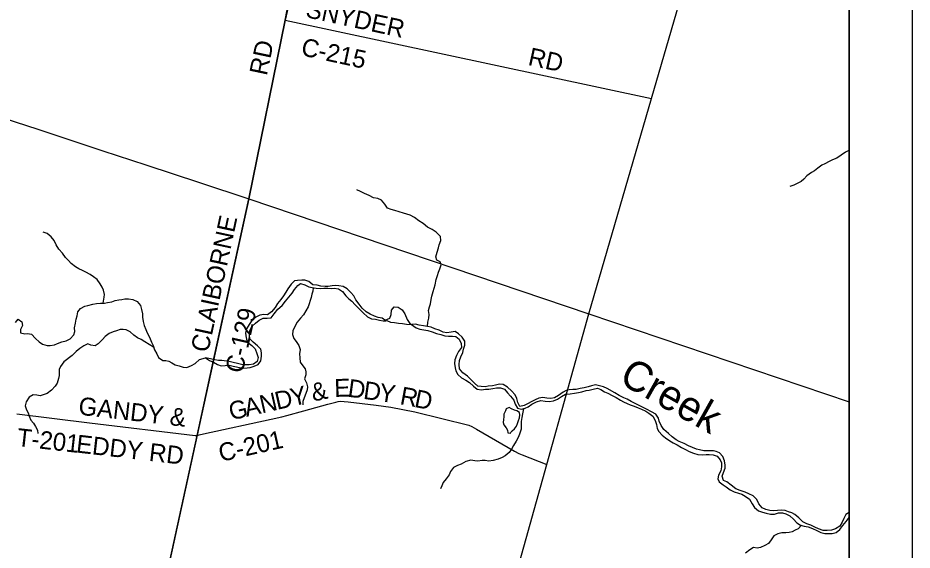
# Model space of a CAD drawing. Extents: x 0 to 34, y 0 to 22.
# Drawn here: x 7.582 to 9, y 16.562 to 17.405 of the extents above; entities that cross this region are included whole.
import ezdxf

# ---------------------------------------------------------------- set-up
doc = ezdxf.new("R2010")
doc.units = 0
for name, color, linetype in [('GM_X_Corporation', 7, 'Continuous'), ('GM_X_County_Road', 7, 'Continuous'), ('GM_X_County_Road_Text', 7, 'Continuous'), ('GM_X_Minor_Lake', 7, 'Continuous'), ('GM_X_Minor_River', 7, 'Continuous'), ('GM_X_Minor_River_Text', 7, 'Continuous'), ('GM_X_Township_Road', 7, 'Continuous'), ('GM_X_Township_Road_Text', 7, 'Continuous'), ('SH_Data', 7, 'Continuous')]:
    doc.layers.add(name, color=color, linetype=linetype)

msp = doc.modelspace()

# ---------------------------------------------------------------- linework, layer by layer
at = {"layer": 'GM_X_Corporation'}
for points in [[(2.7052, 14.1), (8.9, 14.1), (8.9, 20.9), (3.3687, 20.9)], [(8.0146, 17.4385), (8.0061, 17.4015), (7.9483, 17.1186), (7.8667, 16.7439), (7.8171, 16.5163), (7.6624, 15.7725), (7.761, 15.7513), (7.7853, 15.4515), (7.8145, 15.0705), (8.0549, 15.0964), (8.0668, 14.9397), (8.0887, 14.5411), (8.0986, 14.3711), (8.2117, 14.3797), (8.4217, 14.3956), (8.5553, 14.4065), (8.6255, 14.4123), (8.6725, 14.4163), (8.8777, 14.4334), (8.8814, 14.4337), (8.9, 14.4352), (8.9, 17.4353)]]:
    msp.add_lwpolyline(points, dxfattribs=at)
at = {"layer": 'GM_X_County_Road'}
for p, q in [((7.9484, 17.1184), (8.0062, 17.4013)), ((8.0062, 17.4013), (8.5866, 17.2775)), ((7.8943, 16.8702), (7.9484, 17.1184)), ((7.8901, 16.8507), (7.8943, 16.8702))]:
    msp.add_line(p, q, dxfattribs=at)
for points in [[(8.3418, 16.4142), (8.4211, 16.6978), (8.4874, 16.9362), (8.5866, 17.2775), (8.6502, 17.4955), (8.6767, 17.5875), (8.6775, 17.5904)], [(8.0062, 17.4013), (8.0122, 17.4314), (8.0127, 17.4363), (8.0124, 17.4394)], [(7.1249, 17.408), (7.1305, 17.405), (7.1344, 17.4026), (7.1425, 17.3964), (7.1511, 17.391), (7.1923, 17.3668), (7.2004, 17.3628), (7.21, 17.3587), (7.3163, 17.3189), (7.3259, 17.3164), (7.348, 17.3113), (7.3805, 17.3035), (7.3867, 17.3018), (7.3932, 17.2999), (7.6139, 17.2289), (7.6678, 17.2109), (7.717, 17.1947), (7.785, 17.1725), (7.8702, 17.1443), (7.9484, 17.1184)], [(7.9484, 17.1184), (8.4874, 16.9362), (8.9, 16.7968)], [(7.6636, 15.7772), (7.8172, 16.516), (7.8668, 16.7436), (7.8901, 16.8507)], [(7.8668, 16.7436), (7.8699, 16.7446), (7.8766, 16.7459), (7.984, 16.7692), (8.001, 16.7731), (8.009, 16.775), (8.0359, 16.7825), (8.0549, 16.7877), (8.0737, 16.793), (8.0862, 16.7963), (8.0899, 16.7971), (8.0946, 16.7977), (8.0994, 16.7976), (8.1058, 16.7969), (8.1503, 16.7916), (8.1739, 16.7886), (8.2115, 16.781), (8.2971, 16.7596), (8.3021, 16.7576), (8.3096, 16.7535), (8.3698, 16.7186), (8.3768, 16.7149), (8.382, 16.7129), (8.4211, 16.6978)]]:
    msp.add_lwpolyline(points, dxfattribs=at)
at = {"layer": 'GM_X_Minor_Lake'}
for points in [[(8.3564, 16.7858), (8.3553, 16.7824), (8.353, 16.7773), (8.3528, 16.7729), (8.3522, 16.7686), (8.3518, 16.764), (8.3529, 16.7602), (8.3567, 16.7557), (8.3584, 16.7519), (8.3589, 16.7475), (8.3631, 16.7473), (8.3645, 16.7493)], [(8.3645, 16.7493), (8.3658, 16.7511), (8.3696, 16.7541), (8.3726, 16.7581), (8.3745, 16.7624), (8.3762, 16.767), (8.3778, 16.7717), (8.3782, 16.7763), (8.3774, 16.7801), (8.3735, 16.7824), (8.3695, 16.7837), (8.3651, 16.7858), (8.361, 16.7879), (8.3564, 16.7858)]]:
    msp.add_lwpolyline(points, dxfattribs=at)
at = {"layer": 'GM_X_Minor_River'}
for points in [[(8.9, 17.1952), (8.8999, 17.1951), (8.8942, 17.1921), (8.8875, 17.1877), (8.8809, 17.183), (8.874, 17.1802), (8.8685, 17.1774), (8.8619, 17.1738), (8.8571, 17.1715), (8.8507, 17.167), (8.8453, 17.1628), (8.8404, 17.16), (8.8332, 17.1549), (8.8286, 17.1498), (8.8239, 17.146), (8.8187, 17.1434), (8.8125, 17.1402), (8.806, 17.1381)], [(8.2316, 16.9164), (8.2324, 16.9229), (8.2341, 16.9295), (8.2342, 16.9352), (8.2336, 16.9417), (8.235, 16.9474), (8.2363, 16.9521), (8.2377, 16.9587), (8.2388, 16.964), (8.2409, 16.9714), (8.2423, 16.9769), (8.244, 16.9824), (8.2457, 16.9906), (8.2477, 16.9972), (8.2494, 17.0025), (8.2513, 17.0073), (8.2534, 17.0137), (8.2521, 17.0188), (8.2463, 17.0213), (8.2448, 17.0266), (8.2472, 17.034), (8.249, 17.0407), (8.2505, 17.0456), (8.253, 17.0522), (8.2525, 17.0585), (8.2457, 17.0657), (8.2394, 17.0697), (8.2319, 17.0737), (8.2249, 17.0793), (8.2182, 17.0835), (8.2113, 17.0886), (8.2041, 17.0926), (8.199, 17.0942), (8.1935, 17.0955), (8.187, 17.0976), (8.1798, 17.0997), (8.1743, 17.1016), (8.1681, 17.1038), (8.1639, 17.1102), (8.1588, 17.1163), (8.1532, 17.119), (8.1462, 17.1202), (8.1392, 17.1238), (8.132, 17.127), (8.1257, 17.1299), (8.1197, 17.1328)], [(7.7175, 16.9533), (7.7193, 16.9624), (7.7195, 16.9671), (7.7184, 16.9737), (7.7162, 16.9785), (7.7131, 16.984), (7.7079, 16.9905), (7.7024, 16.9949), (7.6969, 16.9987), (7.6903, 17.0023), (7.6846, 17.005), (7.6793, 17.0077), (7.6736, 17.0109), (7.6668, 17.0159), (7.6625, 17.0208), (7.658, 17.0256), (7.6529, 17.0322), (7.6476, 17.0389), (7.6432, 17.0457), (7.64, 17.0526), (7.6351, 17.0581), (7.6287, 17.0634), (7.6223, 17.0657)], [(8.1655, 16.9254), (8.1598, 16.9294), (8.1537, 16.9304), (8.1475, 16.9325), (8.1409, 16.9358), (8.1346, 16.9394), (8.1284, 16.9453), (8.1233, 16.9514), (8.1184, 16.9582), (8.1152, 16.9649), (8.1101, 16.9702), (8.1043, 16.9757), (8.098, 16.9794), (8.0914, 16.9807), (8.0866, 16.9809), (8.0806, 16.9804), (8.0745, 16.9796), (8.0694, 16.9795), (8.0629, 16.9799), (8.0569, 16.9816), (8.0502, 16.9824), (8.0434, 16.9873), (8.0372, 16.9898), (8.0323, 16.9897), (8.0258, 16.9891), (8.0211, 16.9886), (8.0159, 16.9833), (8.0106, 16.9759), (8.007, 16.9704), (8.0035, 16.9647), (7.999, 16.9589), (7.994, 16.9528), (7.9902, 16.9462), (7.9843, 16.9394), (7.9782, 16.9346), (7.9721, 16.9352), (7.9659, 16.9339), (7.9594, 16.9311), (7.9533, 16.9258), (7.9489, 16.9196), (7.9449, 16.9126), (7.9434, 16.9059), (7.9439, 16.9012), (7.9447, 16.8963), (7.9467, 16.8906), (7.9532, 16.886), (7.9586, 16.8806), (7.9613, 16.8732), (7.9631, 16.8668), (7.9618, 16.8605), (7.9557, 16.8564), (7.9489, 16.8553), (7.9419, 16.8557), (7.9371, 16.8562), (7.9305, 16.8574), (7.9237, 16.8593), (7.9174, 16.8607), (7.9055, 16.8621), (7.9006, 16.8625), (7.8947, 16.8634), (7.888, 16.8652), (7.8801, 16.8663)], [(7.8801, 16.8663), (7.886, 16.8621), (7.8924, 16.8596), (7.8986, 16.8562), (7.9047, 16.8541), (7.9108, 16.8543), (7.9172, 16.8548), (7.9238, 16.8535), (7.9288, 16.8523), (7.9356, 16.8506), (7.9403, 16.85), (7.946, 16.8505), (7.9509, 16.8511), (7.9572, 16.8531), (7.9633, 16.856), (7.9675, 16.8618), (7.9688, 16.869), (7.9685, 16.8742), (7.9674, 16.8804), (7.9621, 16.8854), (7.9555, 16.8913), (7.9494, 16.897), (7.9496, 16.9029), (7.9502, 16.9091), (7.9531, 16.916), (7.959, 16.9216), (7.9651, 16.926), (7.9715, 16.9295), (7.9778, 16.9295), (7.9841, 16.9299), (7.9888, 16.9363), (7.9947, 16.9437), (8.0012, 16.9497), (8.0069, 16.9562), (8.0119, 16.9626), (8.0172, 16.9688), (8.021, 16.9747), (8.026, 16.9811), (8.0307, 16.9845), (8.0373, 16.9824), (8.0436, 16.9792), (8.0487, 16.978), (8.0555, 16.9767), (8.0616, 16.9763), (8.0675, 16.9768), (8.0737, 16.9768), (8.0788, 16.9766), (8.0838, 16.9768), (8.0908, 16.976), (8.0972, 16.9716), (8.1021, 16.9649), (8.107, 16.96), (8.1119, 16.9564), (8.1172, 16.9503), (8.1297, 16.9377), (8.1365, 16.9314), (8.1431, 16.9285), (8.1494, 16.9276), (8.1556, 16.926), (8.1615, 16.9251), (8.1655, 16.9254)], [(8.0506, 16.9776), (8.0498, 16.9723), (8.0483, 16.9676), (8.0471, 16.9621), (8.046, 16.9574), (8.0444, 16.9522), (8.0427, 16.9473), (8.0391, 16.9409), (8.0351, 16.9346), (8.0307, 16.9295), (8.0254, 16.9229), (8.0215, 16.9161), (8.0183, 16.9095), (8.0175, 16.9036), (8.0198, 16.8971), (8.0235, 16.8922), (8.0277, 16.8863), (8.0299, 16.8796), (8.029, 16.873), (8.0295, 16.8665), (8.0298, 16.8599), (8.0342, 16.8536), (8.0378, 16.8489), (8.0389, 16.8441), (8.0387, 16.8394), (8.0369, 16.8331), (8.0398, 16.827), (8.0414, 16.8208), (8.041, 16.816), (8.0389, 16.81), (8.0363, 16.8031), (8.0343, 16.7971), (8.0341, 16.7921)], [(7.6737, 16.9214), (7.6746, 16.928), (7.6764, 16.9329), (7.6777, 16.9394), (7.6817, 16.9447), (7.6884, 16.9482), (7.6933, 16.9497), (7.7011, 16.9514), (7.707, 16.9524), (7.7134, 16.9531), (7.7195, 16.9534), (7.7244, 16.954), (7.7314, 16.9555), (7.7366, 16.9572), (7.7422, 16.9583), (7.7474, 16.9592), (7.7521, 16.9598), (7.758, 16.9599), (7.7648, 16.9592), (7.7716, 16.9557), (7.7767, 16.9496), (7.7784, 16.9432), (7.7799, 16.936), (7.7802, 16.9308), (7.7812, 16.9242), (7.7827, 16.9177), (7.7853, 16.9113), (7.7872, 16.9063), (7.7898, 16.9016), (7.792, 16.8966), (7.7945, 16.8913), (7.7967, 16.886), (7.799, 16.8792), (7.8026, 16.8729), (7.8054, 16.867), (7.812, 16.8624), (7.8169, 16.8622), (7.8217, 16.8612), (7.8266, 16.8587), (7.8317, 16.8553), (7.838, 16.8536), (7.8446, 16.8515), (7.8503, 16.8514), (7.8575, 16.8543), (7.8636, 16.8577), (7.8702, 16.8637), (7.8801, 16.8663)], [(8.1647, 16.926), (8.1719, 16.9294), (8.1744, 16.9354), (8.1748, 16.9419), (8.179, 16.9472), (8.1853, 16.9466), (8.1915, 16.9426), (8.1957, 16.9363), (8.1993, 16.9274), (8.2046, 16.9196)], [(7.5787, 16.9227), (7.5829, 16.9276), (7.5889, 16.9238), (7.5895, 16.9175), (7.5868, 16.9112), (7.5866, 16.9063), (7.5932, 16.9044), (7.5979, 16.9051), (7.6038, 16.9038), (7.6106, 16.8973), (7.6159, 16.8918), (7.6214, 16.8882), (7.6288, 16.886), (7.6337, 16.886), (7.6403, 16.8873), (7.6451, 16.8894), (7.6519, 16.892), (7.6589, 16.8935), (7.6652, 16.8965), (7.6711, 16.9028), (7.6727, 16.9083), (7.6723, 16.9143), (7.6737, 16.9214)], [(8.1655, 16.9254), (8.1672, 16.9256), (8.1731, 16.9233), (8.1795, 16.9225), (8.1859, 16.9215), (8.1922, 16.9208), (8.1983, 16.9198), (8.2062, 16.9196)], [(8.7065, 16.6702), (8.7012, 16.6723), (8.6991, 16.6791), (8.7011, 16.685), (8.7034, 16.6916), (8.7038, 16.6966), (8.7025, 16.7032), (8.6998, 16.7104), (8.6947, 16.7161), (8.6896, 16.7184), (8.6849, 16.719), (8.6796, 16.7194), (8.6747, 16.7191), (8.6699, 16.7191), (8.6631, 16.7206), (8.6582, 16.722), (8.6519, 16.7243), (8.6455, 16.7273), (8.6385, 16.7308), (8.6309, 16.7342), (8.626, 16.7367), (8.6194, 16.7414), (8.6137, 16.7466), (8.6063, 16.7531), (8.602, 16.7593), (8.5992, 16.7662), (8.5981, 16.7709), (8.5936, 16.7772), (8.5871, 16.7808), (8.5788, 16.7852), (8.5727, 16.7885), (8.5674, 16.7911), (8.5612, 16.7942), (8.5546, 16.7975), (8.5481, 16.8009), (8.5432, 16.8034), (8.5357, 16.8068), (8.5288, 16.811), (8.5167, 16.8179), (8.5107, 16.8204), (8.5042, 16.8223), (8.4982, 16.8236), (8.4915, 16.8223), (8.4864, 16.8208), (8.4802, 16.819), (8.4737, 16.8182), (8.4673, 16.8165), (8.4619, 16.8166), (8.4566, 16.8158), (8.4517, 16.8149), (8.4466, 16.8123), (8.4395, 16.8066), (8.4331, 16.8034), (8.4272, 16.8023), (8.4209, 16.8029), (8.4145, 16.8036), (8.4082, 16.8029), (8.4022, 16.8001), (8.3959, 16.7967), (8.3911, 16.7942), (8.3849, 16.7909), (8.3784, 16.7895), (8.3748, 16.7958), (8.3732, 16.8019), (8.3705, 16.8078), (8.3651, 16.8143), (8.3588, 16.8202), (8.3518, 16.8244), (8.3458, 16.8248), (8.3397, 16.8231), (8.3349, 16.8223), (8.3281, 16.8216), (8.3232, 16.8207), (8.3167, 16.8209), (8.3118, 16.8219), (8.3061, 16.8264), (8.3009, 16.8319), (8.295, 16.8375), (8.2876, 16.843), (8.2823, 16.8491), (8.2822, 16.8559), (8.2824, 16.8622), (8.2845, 16.8679), (8.2876, 16.8749), (8.2889, 16.88), (8.2908, 16.8868), (8.2907, 16.8931), (8.2865, 16.8992), (8.281, 16.9047), (8.2754, 16.9083), (8.2691, 16.9072), (8.2625, 16.9059), (8.2568, 16.9072), (8.25, 16.9101), (8.2435, 16.9126), (8.2375, 16.9151), (8.2316, 16.9164), (8.2254, 16.9174), (8.2187, 16.9182), (8.2129, 16.9201), (8.2062, 16.9196)], [(8.2062, 16.9196), (8.2138, 16.914), (8.2198, 16.9121), (8.2261, 16.9108), (8.2325, 16.9098), (8.2392, 16.9077), (8.2462, 16.9052), (8.253, 16.9033), (8.259, 16.9015), (8.2651, 16.901), (8.2714, 16.9009), (8.2765, 16.9002), (8.2822, 16.8961), (8.285, 16.8893), (8.2855, 16.883), (8.2811, 16.8768), (8.2777, 16.87), (8.275, 16.8634), (8.2748, 16.8575), (8.2757, 16.8508), (8.2768, 16.8461), (8.2797, 16.84), (8.2859, 16.835), (8.2923, 16.8312), (8.2984, 16.8272), (8.3046, 16.8217), (8.3105, 16.8171), (8.3173, 16.8156), (8.3239, 16.8167), (8.3289, 16.817), (8.3353, 16.8182), (8.3414, 16.8191), (8.3474, 16.8191), (8.3537, 16.8168), (8.3586, 16.8109), (8.3635, 16.8059), (8.3688, 16.7996), (8.3708, 16.793), (8.3746, 16.7867), (8.3807, 16.785), (8.3866, 16.7867), (8.3913, 16.7889), (8.3974, 16.7929), (8.4044, 16.7969), (8.4116, 16.7991), (8.4181, 16.7978), (8.4249, 16.7972), (8.4315, 16.7983), (8.4378, 16.8013), (8.4441, 16.8054), (8.4507, 16.8088), (8.4577, 16.8096), (8.465, 16.8105), (8.471, 16.8114), (8.4762, 16.8127), (8.4834, 16.8146), (8.4881, 16.8155), (8.4946, 16.817), (8.5014, 16.8183), (8.5067, 16.8166), (8.5126, 16.8126), (8.5177, 16.8103), (8.5247, 16.8069), (8.5311, 16.8038), (8.5375, 16.7994), (8.5424, 16.7969), (8.5481, 16.7943), (8.553, 16.7923), (8.5595, 16.7897), (8.5657, 16.7872), (8.5712, 16.7851), (8.5778, 16.782), (8.5828, 16.7788), (8.5892, 16.7742), (8.5929, 16.7675), (8.5946, 16.7607), (8.5959, 16.7548), (8.5986, 16.7499), (8.604, 16.744), (8.6093, 16.7396), (8.6159, 16.7348), (8.6214, 16.732), (8.6277, 16.7287), (8.6345, 16.7245), (8.6405, 16.7213), (8.6468, 16.718), (8.6536, 16.7157), (8.6604, 16.7136), (8.667, 16.7128), (8.6735, 16.7132), (8.6782, 16.7134), (8.6847, 16.7131), (8.6909, 16.7108), (8.6958, 16.7048), (8.6979, 16.7), (8.6979, 16.6936), (8.6969, 16.6875), (8.6933, 16.6805), (8.6921, 16.6746), (8.6942, 16.6699), (8.7004, 16.6655)], [(7.7976, 16.8835), (7.7903, 16.8879), (7.7839, 16.8919), (7.7778, 16.8954), (7.7718, 16.8984), (7.7663, 16.9022), (7.7602, 16.9078), (7.7542, 16.9108), (7.7493, 16.9116), (7.7445, 16.9112), (7.7388, 16.9095), (7.7337, 16.9075), (7.7272, 16.905), (7.7206, 16.9005), (7.7164, 16.8954), (7.7099, 16.8886), (7.7048, 16.8858), (7.6983, 16.8867), (7.6934, 16.8885), (7.6868, 16.8856), (7.6807, 16.8813), (7.6748, 16.8768), (7.6687, 16.8703), (7.6554, 16.8601), (7.6499, 16.853), (7.6481, 16.8482), (7.6479, 16.8435), (7.6479, 16.8384), (7.6469, 16.8336), (7.6448, 16.8266), (7.6416, 16.8217), (7.6357, 16.8152), (7.6288, 16.8098), (7.6224, 16.8077), (7.6176, 16.8064), (7.6127, 16.8074), (7.6066, 16.8078), (7.6002, 16.8042), (7.5956, 16.797), (7.5939, 16.7904), (7.5959, 16.7843), (7.5986, 16.7793), (7.6003, 16.7742), (7.6027, 16.7677), (7.6074, 16.763), (7.6106, 16.758), (7.6133, 16.752), (7.614, 16.7468)], [(8.3837, 16.7859), (8.3825, 16.778), (8.3814, 16.7721), (8.3804, 16.7656), (8.3804, 16.7605), (8.38, 16.7535), (8.3782, 16.747), (8.3758, 16.7414), (8.3725, 16.7344), (8.3683, 16.7279), (8.3649, 16.7219), (8.3613, 16.7168), (8.3548, 16.7115), (8.35, 16.7086), (8.3436, 16.7058), (8.3356, 16.7039), (8.3288, 16.7028), (8.3233, 16.704), (8.3182, 16.704), (8.3117, 16.7029), (8.3066, 16.7031), (8.3005, 16.7043), (8.2924, 16.7024), (8.285, 16.6981), (8.2793, 16.6962), (8.273, 16.693), (8.2682, 16.6865), (8.2663, 16.6811), (8.2615, 16.6746), (8.2564, 16.6688), (8.2543, 16.6638), (8.2522, 16.6591)], [(8.7004, 16.6655), (8.7053, 16.6624), (8.7116, 16.6576), (8.718, 16.6542), (8.725, 16.6521), (8.7301, 16.6504), (8.7356, 16.6475), (8.742, 16.6424), (8.7465, 16.6355), (8.7499, 16.6292), (8.7566, 16.6241), (8.763, 16.622), (8.7685, 16.6206), (8.7753, 16.6191), (8.7821, 16.6191), (8.7884, 16.6211), (8.7946, 16.6211), (8.7998, 16.6196), (8.806, 16.616), (8.812, 16.611), (8.8173, 16.6051), (8.8232, 16.6017), (8.8289, 16.5998), (8.8351, 16.599), (8.8421, 16.5961), (8.8488, 16.5931), (8.8552, 16.59), (8.8614, 16.5881), (8.8671, 16.5881), (8.8732, 16.5884), (8.8795, 16.5899), (8.8853, 16.5945), (8.8903, 16.6011), (8.8956, 16.6071), (8.9, 16.6135)], [(8.9, 16.6213), (8.8947, 16.6185), (8.8919, 16.6121), (8.889, 16.6062), (8.8854, 16.5998), (8.8785, 16.5958), (8.8721, 16.5935), (8.8651, 16.593), (8.8588, 16.5932), (8.8516, 16.5957), (8.8457, 16.5982), (8.8393, 16.6016), (8.8332, 16.6034), (8.8268, 16.6068), (8.8202, 16.6133), (8.814, 16.6184), (8.8091, 16.6209), (8.8041, 16.6228), (8.7988, 16.6245), (8.7926, 16.6251), (8.7865, 16.6249), (8.7795, 16.6242), (8.7744, 16.6246), (8.7683, 16.6263), (8.7623, 16.629), (8.7572, 16.6355), (8.754, 16.6421), (8.7479, 16.6478), (8.7413, 16.6509), (8.7351, 16.6536), (8.7275, 16.6566), (8.7203, 16.6591), (8.7129, 16.665), (8.7065, 16.6702)], [(8.8246, 16.6012), (8.8196, 16.5954), (8.8146, 16.5934), (8.8099, 16.5909), (8.8049, 16.5896), (8.8, 16.5894), (8.7934, 16.5893), (8.7869, 16.5878), (8.7808, 16.5846), (8.7765, 16.5783), (8.7725, 16.5726), (8.7664, 16.569), (8.7594, 16.566), (8.7546, 16.5649), (8.7484, 16.5663), (8.7425, 16.5625), (8.7358, 16.557)]]:
    msp.add_lwpolyline(points, dxfattribs=at)
at = {"layer": 'GM_X_Township_Road'}
msp.add_lwpolyline([(7.5807, 16.7776), (7.6961, 16.7635), (7.8634, 16.7437), (7.8668, 16.7436)], dxfattribs=at)
at = {"layer": 'SH_Data'}
for p, q in [((9, 21), (9, 14)), ((8.9, 20.9), (8.9, 14.1))]:
    msp.add_line(p, q, dxfattribs=at)

# ---------------------------------------------------------------- texts
at = {"layer": 'GM_X_County_Road_Text'}
for s, height, rotation, p in [('SNYDER', 0.02841, 347.8451, (8.0372, 17.4065)), ('RD', 0.02841, 78.112, (7.9769, 17.3125)), ('C-215', 0.02841, 347.8288, (8.0299, 17.3461)), ('RD', 0.02841, 347.63, (8.3898, 17.3307)), ('CLAIBORNE', 0.02841, 77.7712, (7.884, 16.8738)), ('C-129', 0.02841, 77.5611, (7.9385, 16.8408)), ('&', 0.0284, 12.7549, (8.0507, 16.797)), ('E', 0.0284, 1.1657, (8.0842, 16.8046)), ('D', 0.0284, 352.1764, (8.1043, 16.8051)), ('D', 0.0284, 352.0992, (8.129, 16.8017)), ('D', 0.0284, 12.8125, (7.9934, 16.784)), ('Y', 0.0284, 12.8089, (8.0178, 16.7895)), ('Y', 0.0284, 351.7463, (8.1537, 16.7983)), ('R', 0.0284, 349.382, (8.1868, 16.7933)), ('D', 0.0284, 348.4586, (8.2096, 16.789)), ('G', 0.0284, 12.8125, (7.9203, 16.7674)), ('A', 0.0284, 12.8089, (7.9447, 16.7729)), ('N', 0.0284, 12.8132, (7.9691, 16.7784)), ('C-201', 0.02841, 12.7681, (7.9041, 16.7016))]:
    msp.add_text(s, height=height, rotation=rotation, dxfattribs=at).set_placement(p)
at = {"layer": 'GM_X_Minor_River_Text'}
msp.add_text('Creek', height=0.04734, rotation=330.6745, dxfattribs=at).set_placement((8.5333, 16.8278))
at = {"layer": 'GM_X_Township_Road_Text'}
for s, rotation, p in [('GANDY &', 353.463, (7.6774, 16.7767)), ('T-201', 353.5362, (7.5797, 16.727)), ('EDDY RD', 353.4538, (7.6739, 16.7167))]:
    msp.add_text(s, height=0.02841, rotation=rotation, dxfattribs=at).set_placement(p)

doc.saveas('drawing.dxf')
